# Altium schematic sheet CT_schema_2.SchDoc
size 276 x 169 mm
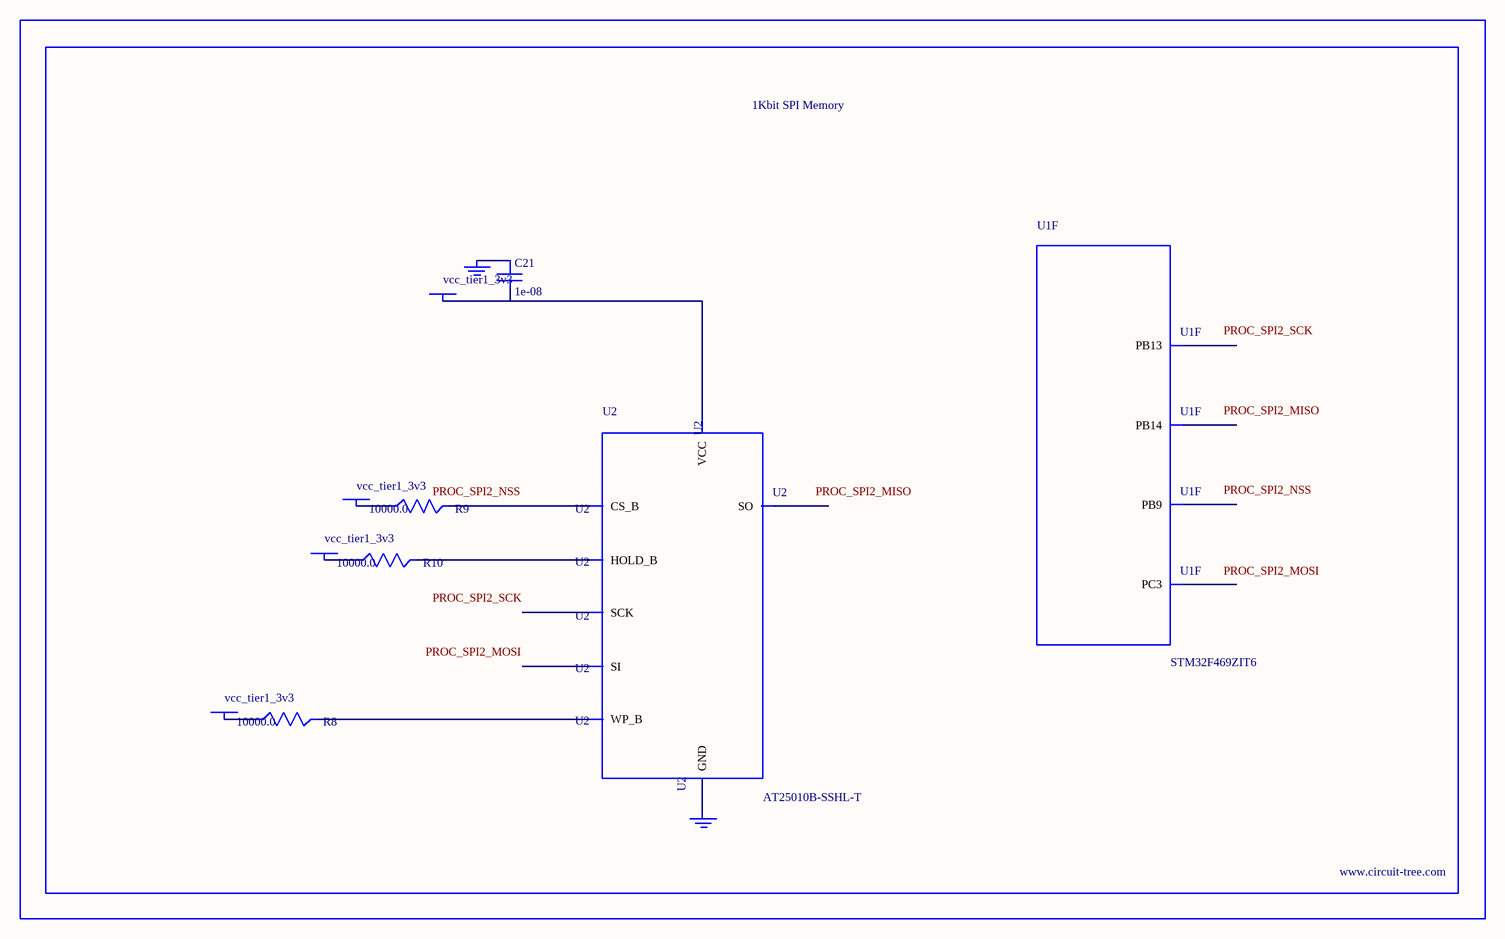
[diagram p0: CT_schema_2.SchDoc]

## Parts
BORDER1  (no value)
C21  1e-08  [C0402]
GND_INSTANCE_1_0  (no value)
GND_INSTANCE_1_1  (no value)
POWER_INSTANCE_1_0  vcc_tier1_3v3
POWER_INSTANCE_1_1  vcc_tier1_3v3
POWER_INSTANCE_1_2  vcc_tier1_3v3
POWER_INSTANCE_1_3  vcc_tier1_3v3
R8  10000.0  [R0603]
R9  10000.0  [R0603]
R10  10000.0  [R0603]
U1  STM32F469ZIT6  [LQFP144]  (part F of 14)
U2  AT25010B-SSHL-T  [SOIC-8]

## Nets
NetC21_1: C21.1 GND_INSTANCE_1_0.0(GND)
NetC21_2: C21.2 POWER_INSTANCE_1_3.0(PWR) U2.8(VCC)
NetGND_INSTANCE_1_1_0: GND_INSTANCE_1_1.0(GND) U2.4(GND)
NetPOWER_INSTANCE_1_0_0: POWER_INSTANCE_1_0.0(PWR) R9.1
NetPOWER_INSTANCE_1_1_0: POWER_INSTANCE_1_1.0(PWR) R8.1
NetPOWER_INSTANCE_1_2_0: POWER_INSTANCE_1_2.0(PWR) R10.1
NetR8_2: R8.2 U2.3(WP_B)
NetR9_2: R9.2 U2.1(CS_B)
NetR10_2: R10.2 U2.7(HOLD_B)

Not connected (* = marked no-connect by the designer): U1 24(PC3) 68(PB13) 69(PB14) 139(PB9); U2 2(SO) 5(SI) 6(SCK)

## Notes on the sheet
- Labels drawn without touching a wire or pin: PROC_SPI2_MISO, PROC_SPI2_MOSI, PROC_SPI2_NSS, PROC_SPI2_SCK

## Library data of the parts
BORDER1 = BORDER_PAGE1
C21 = C0402C103K3RAC
GND_INSTANCE_1_0 GND_INSTANCE_1_1 = GND
POWER_INSTANCE_1_0-POWER_INSTANCE_1_3 = PWR
R8-R10 = RC0603JR-0710KL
